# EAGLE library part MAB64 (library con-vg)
CONNECTOR male, 94 pins, type B, rows AB, grid 2.54 mm
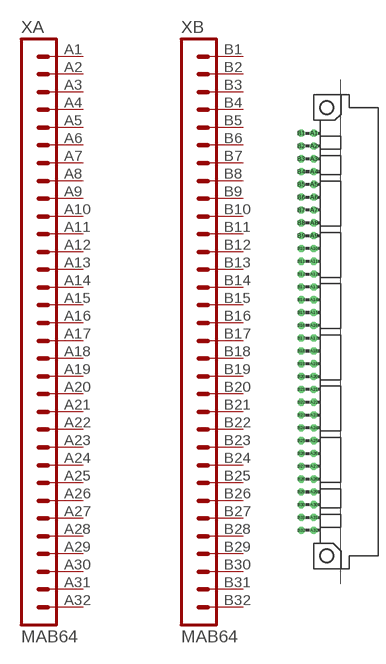
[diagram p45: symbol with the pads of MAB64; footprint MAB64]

Designator prefix X; gates A=M32 B=M32

## MAB64  [MAB64]
A1  A:1  pas
A2  A:2  pas
A3  A:3  pas
A4  A:4  pas
A5  A:5  pas
A6  A:6  pas
A7  A:7  pas
A8  A:8  pas
A9  A:9  pas
A10  A:10  pas
A11  A:11  pas
A12  A:12  pas
A13  A:13  pas
A14  A:14  pas
A15  A:15  pas
A16  A:16  pas
A17  A:17  pas
A18  A:18  pas
A19  A:19  pas
A20  A:20  pas
A21  A:21  pas
A22  A:22  pas
A23  A:23  pas
A24  A:24  pas
A25  A:25  pas
A26  A:26  pas
A27  A:27  pas
A28  A:28  pas
A29  A:29  pas
A30  A:30  pas
A31  A:31  pas
A32  A:32  pas
B1  B:1  pas
B2  B:2  pas
B3  B:3  pas
B4  B:4  pas
B5  B:5  pas
B6  B:6  pas
B7  B:7  pas
B8  B:8  pas
B9  B:9  pas
B10  B:10  pas
B11  B:11  pas
B12  B:12  pas
B13  B:13  pas
B14  B:14  pas
B15  B:15  pas
B16  B:16  pas
B17  B:17  pas
B18  B:18  pas
B19  B:19  pas
B20  B:20  pas
B21  B:21  pas
B22  B:22  pas
B23  B:23  pas
B24  B:24  pas
B25  B:25  pas
B26  B:26  pas
B27  B:27  pas
B28  B:28  pas
B29  B:29  pas
B30  B:30  pas
B31  B:31  pas
B32  B:32  pas

## Footprint MAB64 (pad centres in mm)
CONNECTOR male, 64 pins, type b, rows AB, grid 2.54 mm
drill 0.914 octagon: A1 -2.54,39.37; A2 -2.54,36.83; A3 -2.54,34.29; A4 -2.54,31.75; A5 -2.54,29.21; A6 -2.54,26.67; A7 -2.54,24.13; A8 -2.54,21.59; A9 -2.54,19.05; A10 -2.54,16.51; A11 -2.54,13.97; A12 -2.54,11.43; A13 -2.54,8.89; A14 -2.54,6.35; A15 -2.54,3.81; A16 -2.54,1.27; A17 -2.54,-1.27; A18 -2.54,-3.81; A19 -2.54,-6.35; A20 -2.54,-8.89; A21 -2.54,-11.43; A22 -2.54,-13.97; A23 -2.54,-16.51; A24 -2.54,-19.05; A25 -2.54,-21.59; A26 -2.54,-24.13; A27 -2.54,-26.67; A28 -2.54,-29.21; A29 -2.54,-31.75; A30 -2.54,-34.29; A31 -2.54,-36.83; A32 -2.54,-39.37; B1 -5.08,39.37; B2 -5.08,36.83; B3 -5.08,34.29; B4 -5.08,31.75; B5 -5.08,29.21; B6 -5.08,26.67; B7 -5.08,24.13; B8 -5.08,21.59; B9 -5.08,19.05; B10 -5.08,16.51; B11 -5.08,13.97; B12 -5.08,11.43; B13 -5.08,8.89; B14 -5.08,6.35; B15 -5.08,3.81; B16 -5.08,1.27; B17 -5.08,-1.27; B18 -5.08,-3.81; B19 -5.08,-6.35; B20 -5.08,-8.89; B21 -5.08,-11.43; B22 -5.08,-13.97; B23 -5.08,-16.51; B24 -5.08,-19.05; B25 -5.08,-21.59; B26 -5.08,-24.13; B27 -5.08,-26.67; B28 -5.08,-29.21; B29 -5.08,-31.75; B30 -5.08,-34.29; B31 -5.08,-36.83; B32 -5.08,-39.37
hole 2.794 at 0,44.45
hole 2.794 at 0,-44.45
